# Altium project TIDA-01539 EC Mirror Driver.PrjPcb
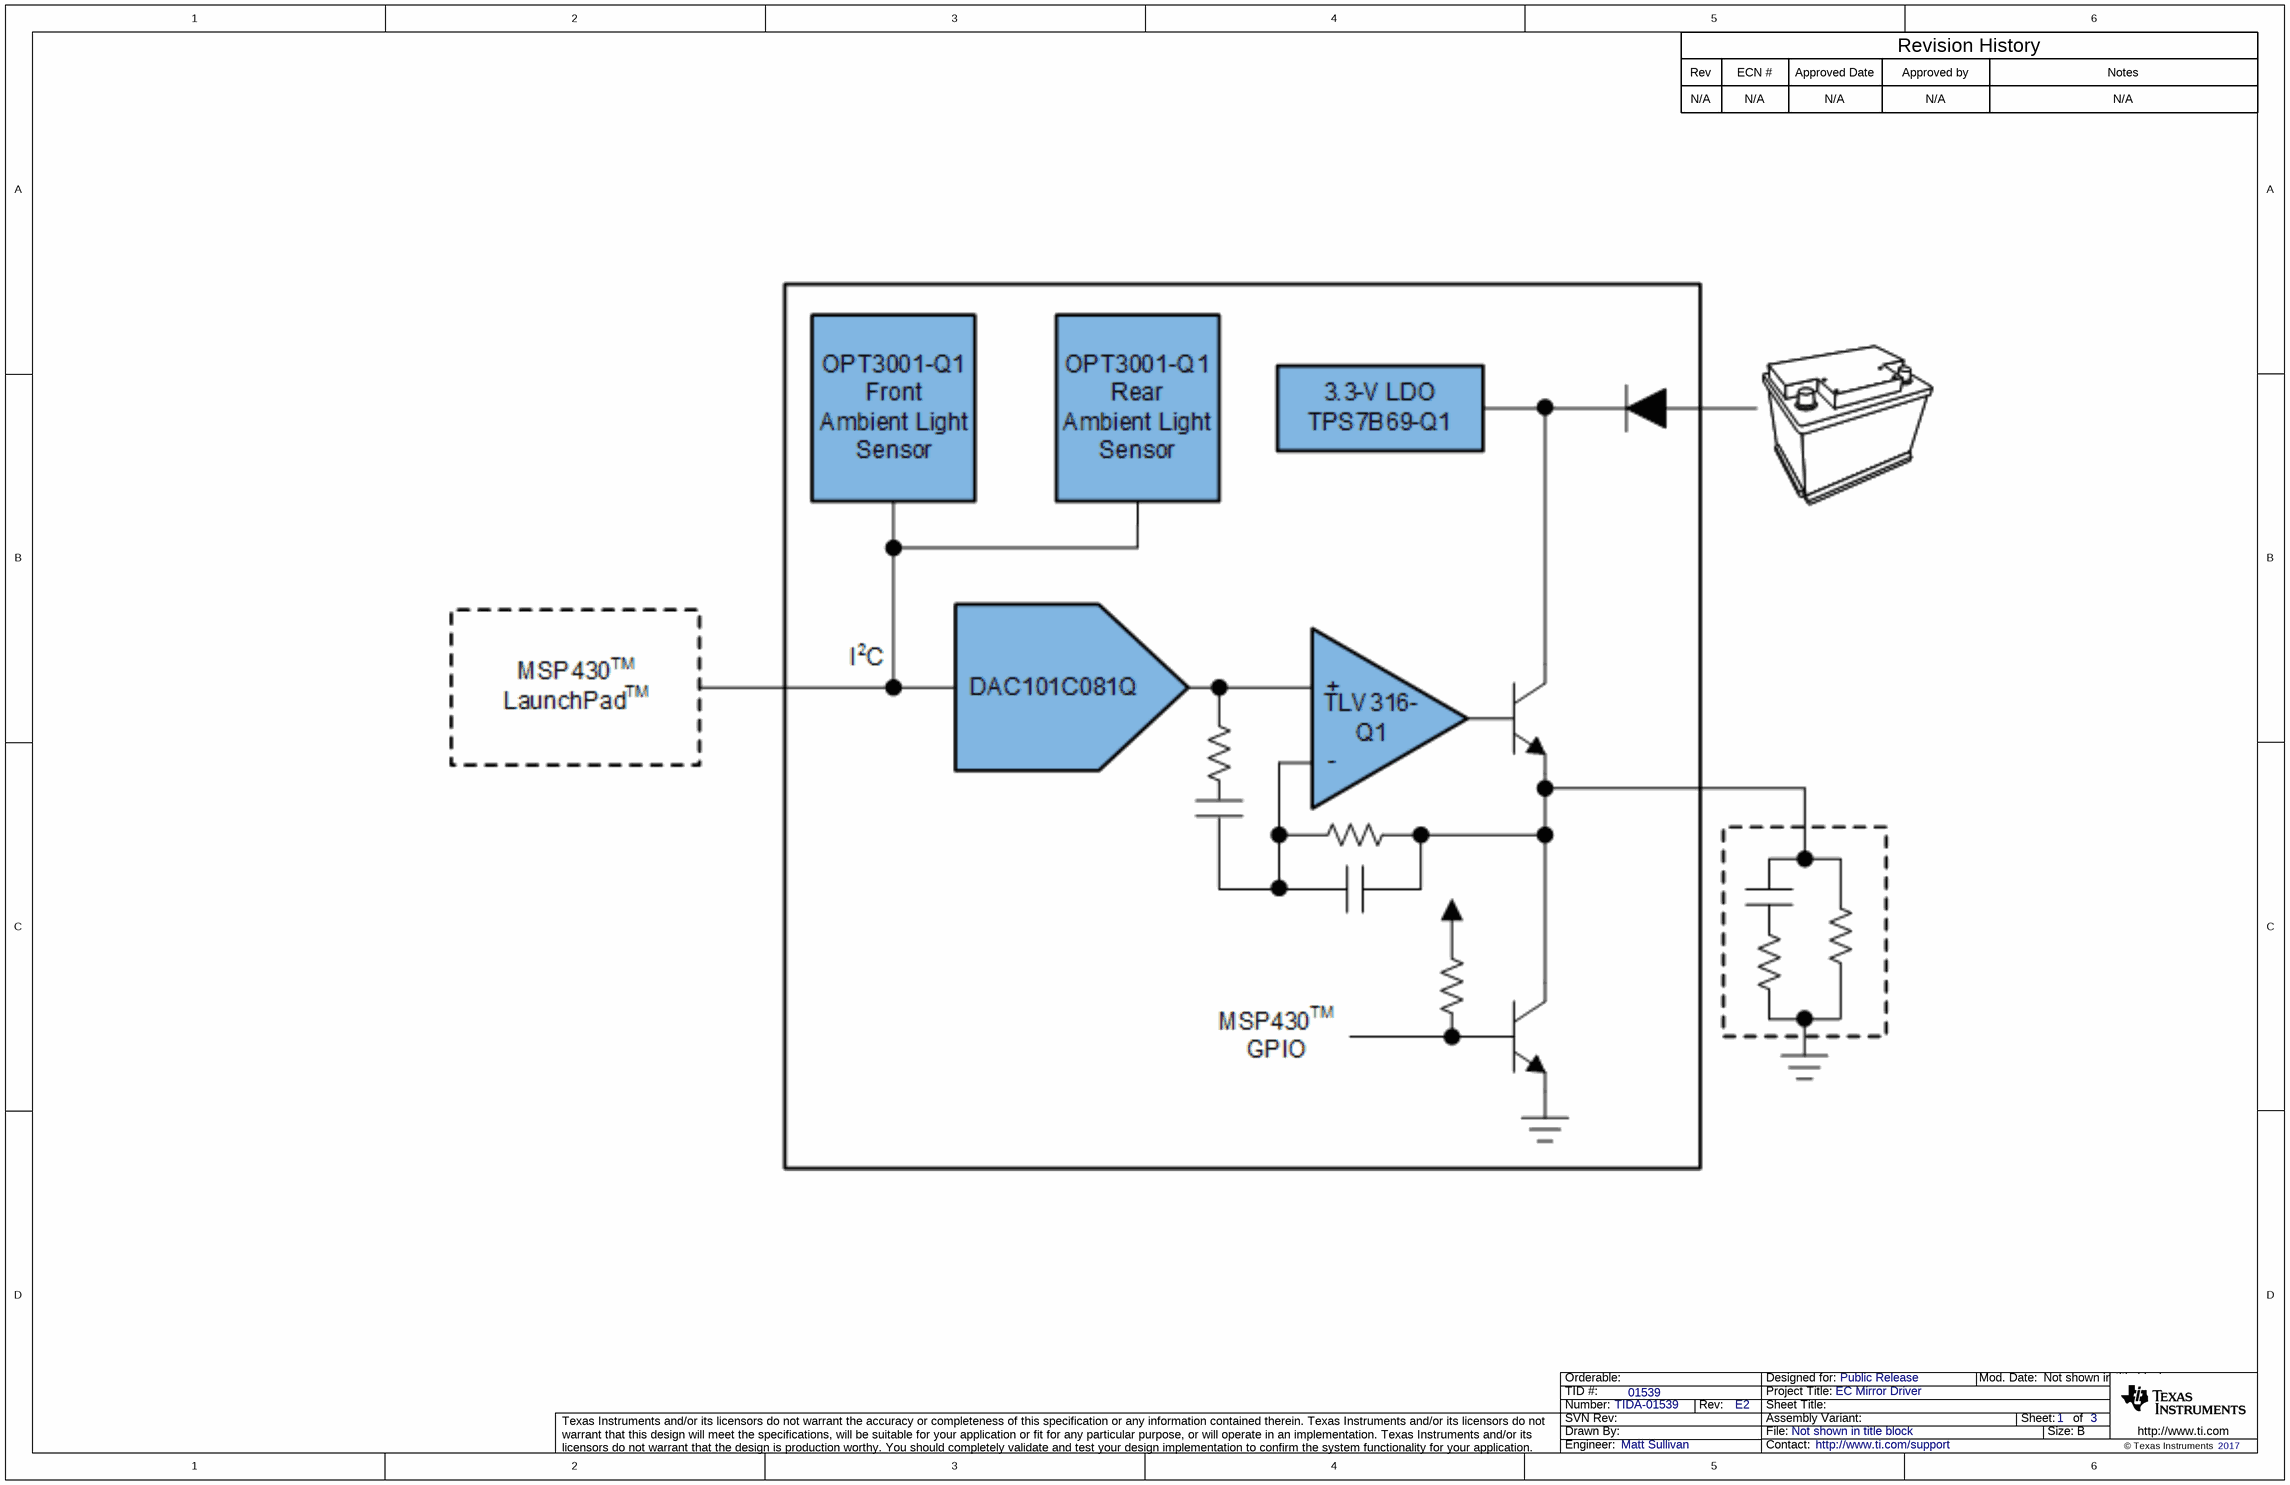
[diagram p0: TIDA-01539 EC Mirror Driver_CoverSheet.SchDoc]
CopyrightYear: 2017; PCB_Layout: Matt Sullivan; PCB_Rev: E2; PRJ_Customer: Public Release; PRJ_Engineer: Matt Sullivan; PRJ_Number: TIDA-01539; PRJ_Title: EC Mirror Driver; SCH_Rev: E2; TechSupport: http://www.ti.com/support; TID: 01539
3 sheets, 46 parts. Net scope: global (net labels, ports and power ports of the same name join across sheets).
Board file: TIDA-01539 EC Mirror Driver_PCB.PcbDoc
Sheets:
  TIDA-01539 EC Mirror Driver_CoverSheet.SchDoc
  TIDA-01539 EC Mirror Driver_EVM_Hardware.SchDoc
  TIDA-01539 EC Mirror Driver_Main.SchDoc

## Sheet TIDA-01539 EC Mirror Driver_CoverSheet.SchDoc
size 431 x 279 mm; Date: Not shown in title block; ApprovedBy: Not shown in title block; CheckedBy: Not shown in title block; Author: Not shown in title block; CompanyName: Not shown in title block; Engineer: Not shown in title block; Organization: Not shown in title block; Address1: Not shown in title block; Address2: Not shown in title block; Address3: Not shown in title block; Address4: Not shown in title block; DocumentNumber: 1; Revision: Use project parameter SCH_Rev; SheetNumber: 1; SheetTotal: 3; PageSetup: Record=PageOptions¦CenterHorizontal=True¦CenterVertical=True¦PrintScale=1.00¦XCorrection=1.00¦YCorrection=1.00¦PrintKind=0¦BorderSize=5000000¦LeftOffset=0¦BottomOffset=0¦Orientation=2¦PaperLength=1000¦PaperWidth=1000¦Scale=100¦PaperSource=15¦PrintQuality=600¦MediaType=1¦DitherType=10¦PaperKind=Letter¦PrintScaleMode=1

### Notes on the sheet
- Rev
- N/A
- ECN #
- Approved Date
- Approved by
- Revision History
- Notes

## Sheet TIDA-01539 EC Mirror Driver_EVM_Hardware.SchDoc
size 431 x 279 mm; Date: Not shown in title block; ApprovedBy: Not shown in title block; CheckedBy: Not shown in title block; Author: Not shown in title block; CompanyName: Not shown in title block; Engineer: Not shown in title block; Organization: Not shown in title block; Address1: Not shown in title block; Address2: Not shown in title block; Address3: Not shown in title block; Address4: Not shown in title block; DocumentNumber: 1; Revision: Use project parameter SCH_Rev; SheetNumber: 3; SheetTotal: 3; PageSetup: Record=PageOptions¦CenterHorizontal=True¦CenterVertical=True¦PrintScale=1.00¦XCorrection=1.00¦YCorrection=1.00¦PrintKind=0¦BorderSize=5000000¦LeftOffset=0¦BottomOffset=0¦Orientation=2¦PaperLength=1000¦PaperWidth=1000¦Scale=100¦PaperSource=15¦PrintQuality=600¦MediaType=1¦DitherType=10¦PaperKind=Letter¦PrintScaleMode=1
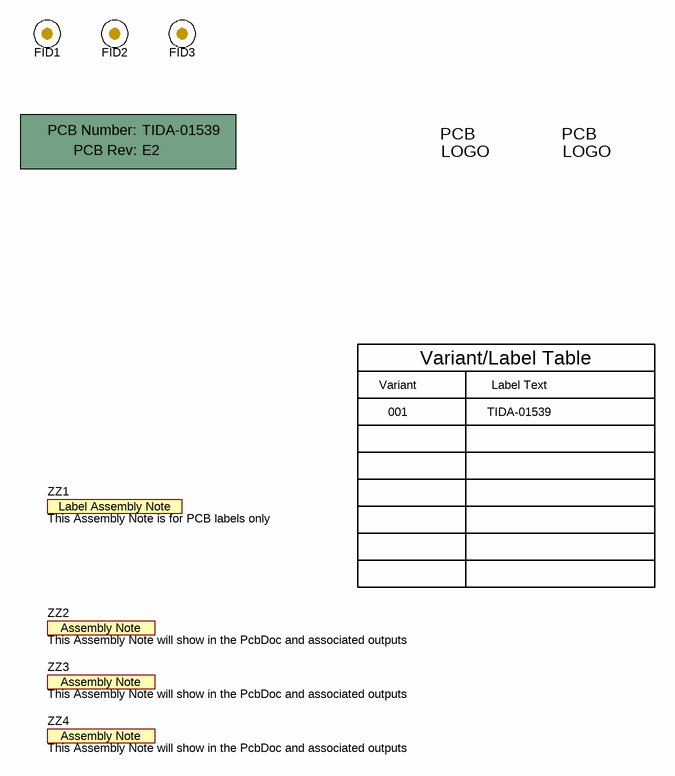
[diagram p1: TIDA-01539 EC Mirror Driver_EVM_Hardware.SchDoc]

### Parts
!PCB1  Printed Circuit Board  (value not drawn)  (mechanical)
FID1  Fiducial  [Fiducial10-20]  (value not drawn)
FID2  Fiducial  [Fiducial10-20]  (value not drawn)
FID3  Fiducial  [Fiducial10-20]  (value not drawn)
Logo2  Pb-Free Symbol  [Pb-Free_Overlay_Small]  (value not drawn)  (no BOM)
Logo3  FCC disclaimer  [FCC_disclaimer]  (value not drawn)  (no BOM)
ZZ1  This Assembly Note is for PCB labels only  [AssemblyNoteLabel]  (no BOM)
ZZ2  This Assembly Note will show in the PcbDoc and associated outputs  [AssemblyNote]  (no BOM)
ZZ3  This Assembly Note will show in the PcbDoc and associated outputs  [AssemblyNote]  (no BOM)
ZZ4  This Assembly Note will show in the PcbDoc and associated outputs  [AssemblyNote]  (no BOM)

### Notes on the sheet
- Variant
- Variant/Label Table
- Label Text
- 001
- TIDA-01539

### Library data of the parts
!PCB1 = PCB: Manufacturer: Any; PartNumber: TIDA-01539; SymbolCreator: a0412235
FID1-FID3 = Fiducial: Fiducial mark.  There is nothing to buy or mount.; SymbolCreator: codlsc
Logo2 = Pb-Free: SymbolCreator: a0412235
Logo3 = FCC_disclaimer: SymbolCreator: a0412235
ZZ1 = AssemblyNoteLabel: SymbolCreator: a0412235
ZZ2-ZZ4 = AssemblyNote: SymbolCreator: codlsc

## Sheet TIDA-01539 EC Mirror Driver_Main.SchDoc
size 431 x 279 mm; Date: Not shown in title block; ApprovedBy: Not shown in title block; CheckedBy: Not shown in title block; Author: Not shown in title block; CompanyName: Not shown in title block; Engineer: Not shown in title block; Organization: Not shown in title block; Address1: Not shown in title block; Address2: Not shown in title block; Address3: Not shown in title block; Address4: Not shown in title block; DocumentNumber: 1; Revision: Use project parameter SCH_Rev; SheetNumber: 2; SheetTotal: 3; PageSetup: Record=PageOptions¦CenterHorizontal=True¦CenterVertical=True¦PrintScale=1.00¦XCorrection=1.00¦YCorrection=1.00¦PrintKind=0¦BorderSize=5000000¦LeftOffset=0¦BottomOffset=0¦Orientation=2¦PaperLength=1000¦PaperWidth=1000¦Scale=100¦PaperSource=15¦PrintQuality=600¦MediaType=1¦DitherType=10¦PaperKind=Letter¦PrintScaleMode=1
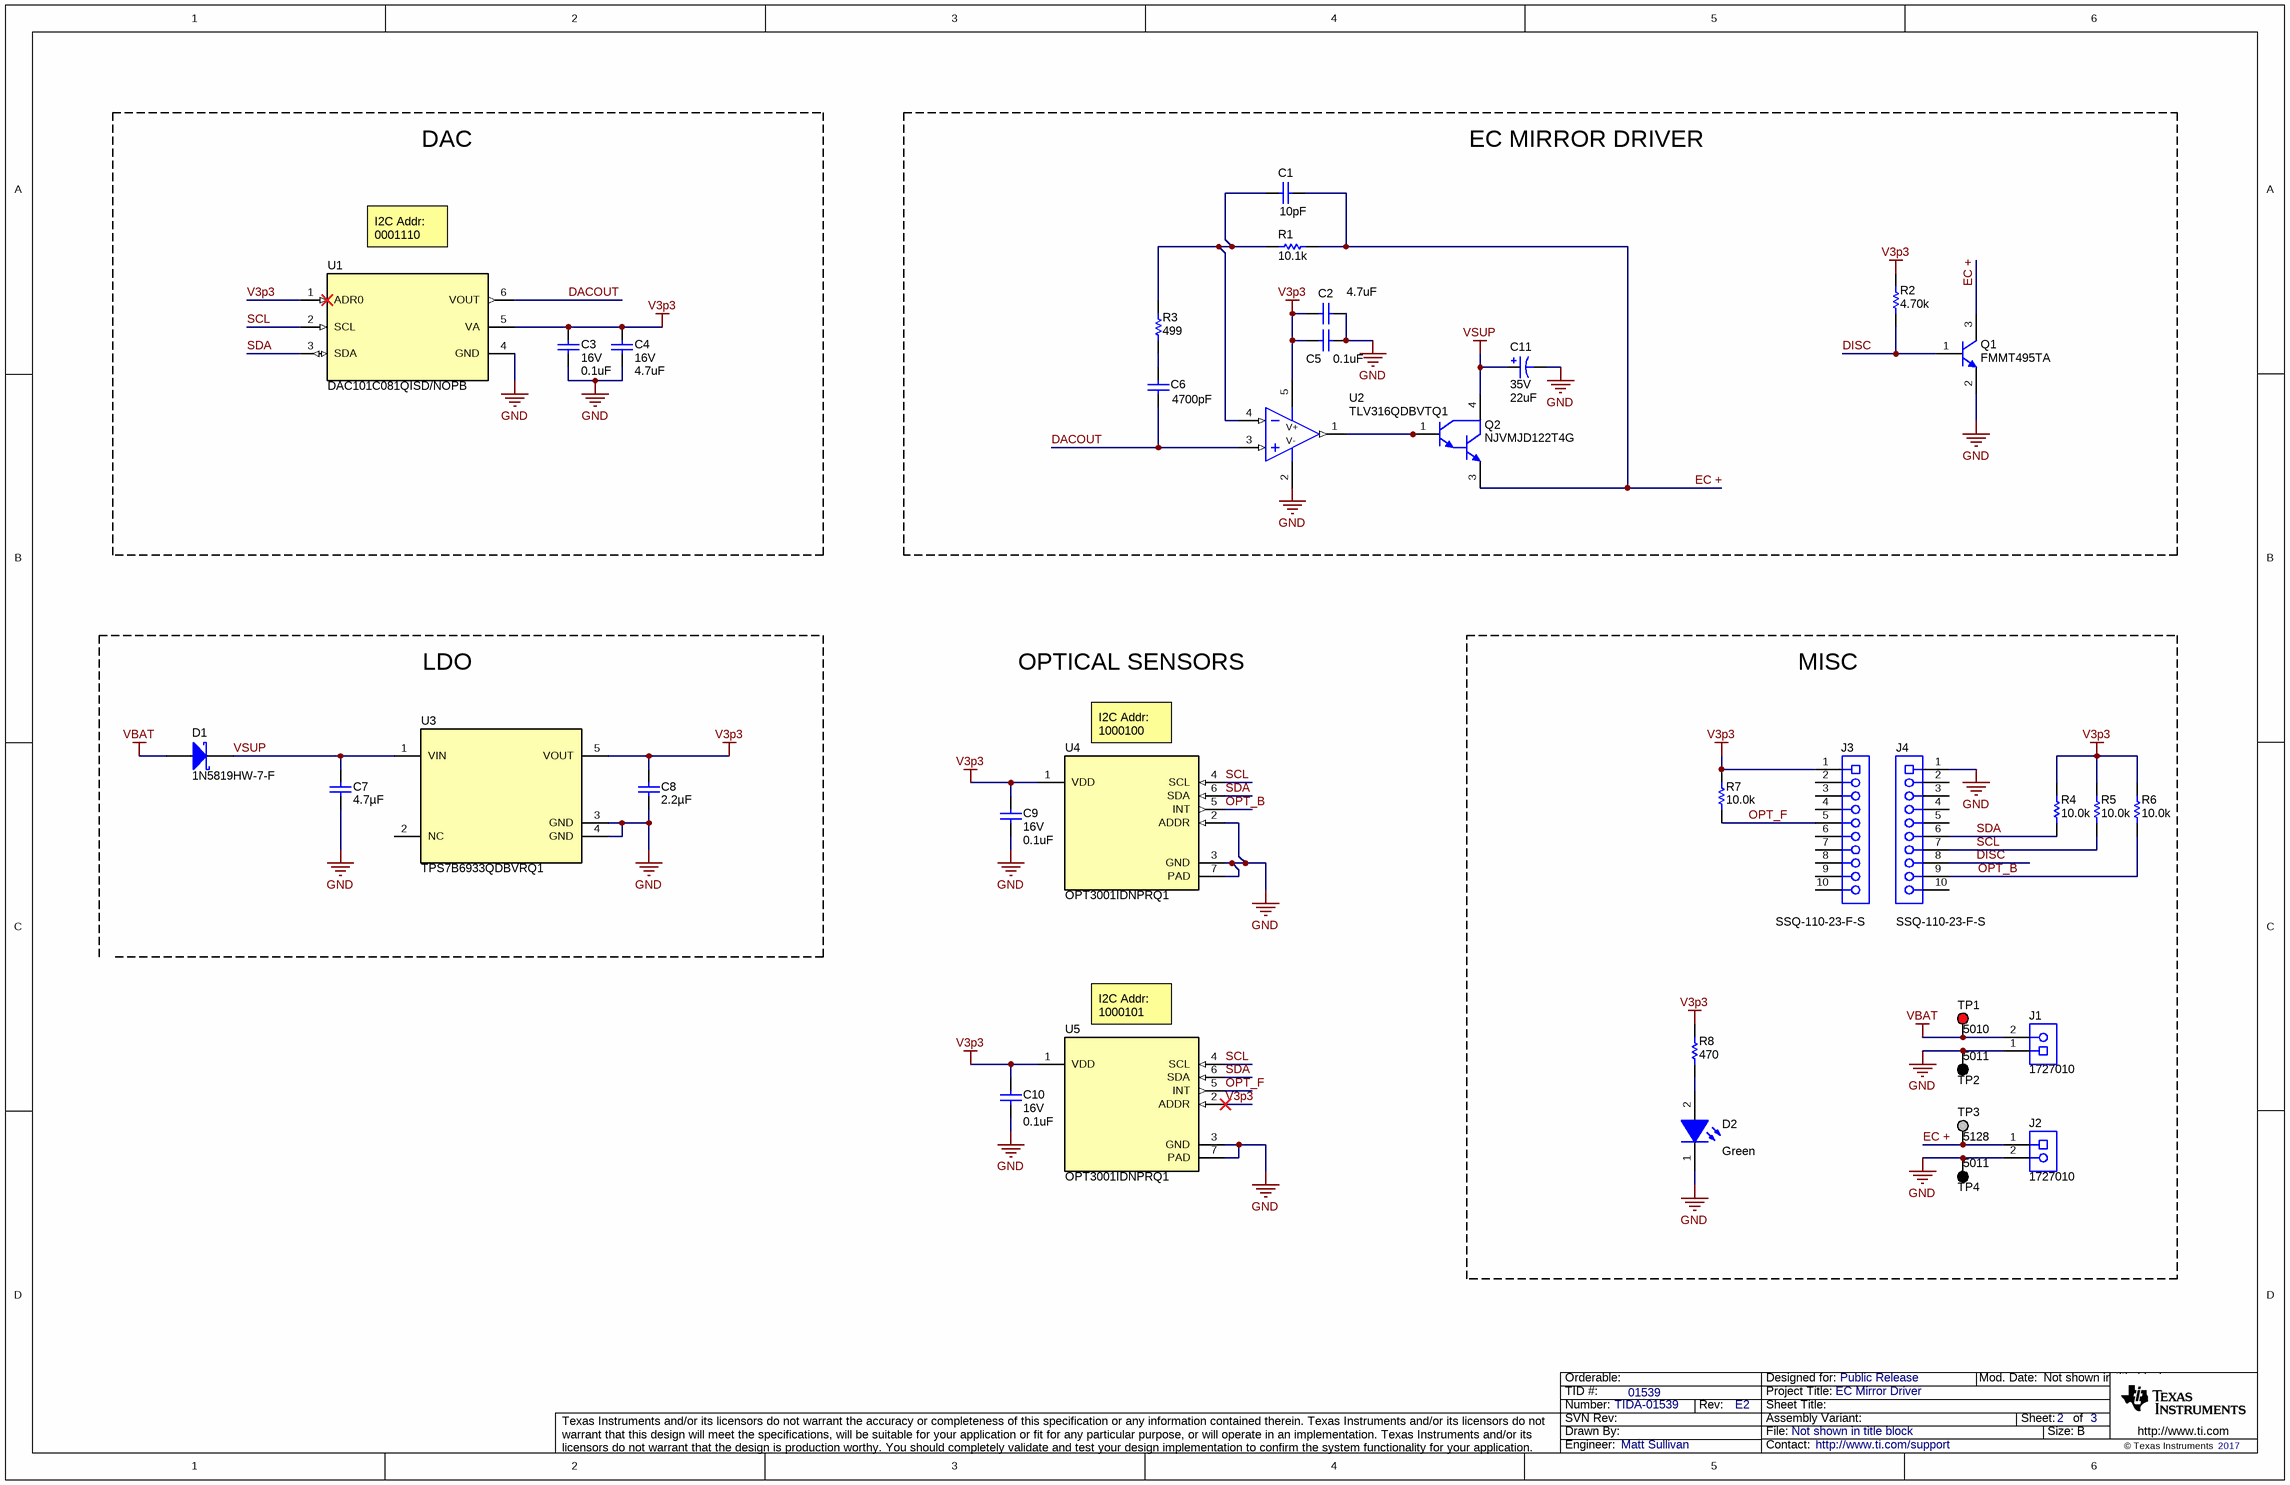
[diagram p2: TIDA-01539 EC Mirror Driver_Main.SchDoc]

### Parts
C1  ValueDisplayed: 10pF  [0603]  (hidden comment: 0603ZC100KAT2A)
C2  ValueDisplayed: 4.7uF  [0603]  (hidden comment: GRM188Z71C475KE21D)
C3  VDC_V: 16V  ValueDisplayed: 0.1uF  [0603]  (hidden comment: GCM188R71C104KA37J)
C4  VDC_V: 16V  ValueDisplayed: 4.7uF  [0603]  (hidden comment: GRM188Z71C475KE21D)
C5  ValueDisplayed: 0.1uF  [0603]  (hidden comment: GCM188R71C104KA37J)
C6  ValueDisplayed: 4700pF  [0603]  (hidden comment: GCM188R71H472KA37D)
C7  ValueDisplayed: 4.7µF  [0805_HV]  (hidden comment: GCM21BR71C475KA73K)
C8  ValueDisplayed: 2.2µF  [0805_HV]  (hidden comment: CGA4J3X7R1E225K125AB)
C9  VDC_V: 16V  ValueDisplayed: 0.1uF  [0603]  (hidden comment: GCM188R71C104KA37J)
C10  VDC_V: 16V  ValueDisplayed: 0.1uF  [0603]  (hidden comment: GCM188R71C104KA37J)
C11  VDC_V: 35V  ValueDisplayed: 22uF  [SM_RADIAL_C]  (hidden comment: EEE-FK1V220R)
D1  1N5819HW-7-F  [SOD-123]
D2  value Green  [WL-SMCW_GREEN]  (hidden comment: 150060GS75000)
J1  1727010  [PhoenixConact_1727010]
J2  1727010  [PhoenixConact_1727010]
J3  SSQ-110-23-F-S  [Samtec_SSQ-110-03-x-S]
J4  SSQ-110-23-F-S  [Samtec_SSQ-110-03-x-S]
Q1  FMMT495TA  [SOT-23]
Q2  NJVMJD122T4G  [DPAK]
R1  ValueDisplayed: 10.1k  [0603]  (hidden comment: RT0603DRE0710K1L)
R2  ValueDisplayed: 4.70k  [0603]  (hidden comment: RC0603FR-074K7L)
R3  ValueDisplayed: 499  [0603]  (hidden comment: CRCW0603499RFKEA)
R4  ValueDisplayed: 10.0k  [0603]  (hidden comment: RMCF0603FT10K0)
R5  ValueDisplayed: 10.0k  [0603]  (hidden comment: RMCF0603FT10K0)
R6  ValueDisplayed: 10.0k  [0603]  (hidden comment: RMCF0603FT10K0)
R7  ValueDisplayed: 10.0k  [0603]  (hidden comment: RMCF0603FT10K0)
R8  ValueDisplayed: 470  [0603]  (hidden comment: RC0603FR-07470RL)
TP1  5010  [Keystone5010]
TP2  5011  [Keystone5011]
TP3  5128  [Keystone5128]
TP4  5011  [Keystone5011]
U1  DAC101C081QISD/NOPB  [NGF0006A]
U2  TLV316QDBVTQ1  [DBV0005A_N]
U3  TPS7B6933QDBVRQ1  [DBV0005A_N]
U4  OPT3001IDNPRQ1  [DNP0006A]
U5  OPT3001IDNPRQ1  [DNP0006A]

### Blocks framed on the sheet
DAC: C3 C4 U1
EC MIRROR DRIVER: C1 C2 C5 C6 C11 Q1 Q2 R1-R3 U2
MISC: D2 J1-J4 R4-R8 TP1-TP4

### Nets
GND: C2.2 C3.2 C4.2 C5.2 C7.2 C8.2 C9.2 C10.2 C11.2(-) D2.1(K) J1.1 J2.2 J4.1 Q1.2(E) TP2.1 TP4.1 U1.4(GND) U2.2(V-) U3.3(GND) U3.4(GND) U4.2(ADDR) U4.3(GND) U4.7(PAD) U5.3(GND) U5.7(PAD)
V3p3: C2.1 C3.1 C4.1 C5.1 C8.1 C9.1 C10.1 J3.1 R2.2 R4.2 R5.2 R6.2 R7.2 R8.2 U1.1(ADR0) U1.5(VA) U2.5(V+) U3.5(VOUT) U4.1(VDD) U5.1(VDD) U5.2(ADDR)
VBAT: D1.2(A) J1.2 TP1.1
VSUP: C7.1 C11.1(+) D1.1(K) Q2.4(C) U3.1(VIN)
DACOUT: C6.2 U1.6(VOUT) U2.3(IN+)
DISC: J4.8 Q1.1(B) R2.1
EC +: C1.1 J2.1 Q1.3(C) Q2.3(E) R1.2 TP3.1
OPT_B: J4.9 R6.1 U4.5(INT)
OPT_F: J3.5 R7.1 U5.5(INT)
SCL: J4.7 R5.1 U1.2(SCL) U4.4(SCL) U5.4(SCL)
SDA: J4.6 R4.1 U1.3(SDA) U4.6(SDA) U5.6(SDA)
NetC1_2: C1.2 R1.1 R3.2 U2.4(IN-)
NetC6_1: C6.1 R3.1
NetD2_2: D2.2(A) R8.1
NetQ2_1: Q2.1(B) U2.1(OUT)

Not connected (* = marked no-connect by the designer): J3 2 3 4 6 7 8 9 10; J4 2 3 4 5 10; U3 2(NC)

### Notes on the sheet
- I2C Addr: 0001110
- LDO
- OPTICAL SENSORS
- (near U4) I2C Addr: 1000100
- (near U5) I2C Addr: 1000101

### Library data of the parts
C1 = CMP-0006811-2: CAP, CERM, 10 pF, 10 V, +/- 10%, X7R, 0603; Manufacturer: AVX; TaMin_C: -55°C; Polarized: N; SizeAreaWB_mm2: 4.68; Value1: Unknown; U/M: EA; Value: 10pF; TaMax_C: 125°C; SizeZ_mm: 1; SizeX_mm: 1.6; SizeY_mm: 0.8; Value2: 10V; SizeArea_mm2: 1.28; AEC Category: Q200
C2 = CMP-0064936-2: CAP, CERM, 4.7 uF, 16 V,+/- 10%, X7R, 0603; Manufacturer: MuRata; TaMin_C: -55°C; Polarized: N; SizeAreaWB_mm2: 4.68; Value1: Unknown; U/M: EA; Value: 4.7uF; TaMax_C: 125°C; SizeZ_mm: 1; SizeX_mm: 1.6; SizeY_mm: 0.8; Value2: 16V; SizeArea_mm2: 1.28; Cap_F: 4.7µF; AEC Category: Q200
C3 C9 C10 = CMP-0007135-2: CAP, CERM, 0.1 uF, 16 V, +/- 10%, X7R, AEC-Q200 Grade 1, 0603; Manufacturer: MuRata; TaMin_C: -55°C; Polarized: N; SizeAreaWB_mm2: 4.68; Value1: Unknown; U/M: EA; Value: 0.1uF; TaMax_C: 125°C; SizeZ_mm: 1; SizeX_mm: 1.6; SizeY_mm: 0.8; SizeArea_mm2: 1.28; AEC Qualified: Y; Cap_F: 100nF; AEC Category: Q200
C4 = CMP-0064936-2: CAP, CERM, 4.7 uF, 16 V,+/- 10%, X7R, 0603; Manufacturer: MuRata; TaMin_C: -55°C; Polarized: N; SizeAreaWB_mm2: 4.68; Value1: Unknown; U/M: EA; Value: 4.7uF; TaMax_C: 125°C; SizeZ_mm: 1; SizeX_mm: 1.6; SizeY_mm: 0.8; SizeArea_mm2: 1.28; Cap_F: 4.7µF; AEC Category: Q200
C5 = CMP-0007135-2: CAP, CERM, 0.1 uF, 16 V, +/- 10%, X7R, AEC-Q200 Grade 1, 0603; Manufacturer: MuRata; TaMin_C: -55°C; Polarized: N; SizeAreaWB_mm2: 4.68; Value1: Unknown; U/M: EA; Value: 0.1uF; TaMax_C: 125°C; SizeZ_mm: 1; SizeX_mm: 1.6; SizeY_mm: 0.8; Value2: 16V; SizeArea_mm2: 1.28; AEC Qualified: Y; Cap_F: 100nF; AEC Category: Q200
C6 = CMP-0007146-2: CAP, CERM, 4700 pF, 50 V, +/- 10%, X7R, AEC-Q200 Grade 1, 0603; Manufacturer: MuRata; TaMin_C: -55°C; Polarized: N; SizeAreaWB_mm2: 4.68; Value1: Unknown; U/M: EA; Value: 4700pF; TaMax_C: 125°C; SizeZ_mm: 1; SizeX_mm: 1.6; SizeY_mm: 0.8; Value2: 50V; SizeArea_mm2: 1.28; AEC Qualified: Y; Cap_F: 4.7nF; AEC Category: Q200
C7 = GCM21BR71C475KA73K: CAP, CERM, 4.7 µF, 16 V, +/- 10%, X7R, AEC-Q200 Grade 1, 0805; Manufacturer: MuRata; Polarized: N; CompType: Capacitor; Value: 4.7uF; U/M: EA; Cap_F: 0.0000047; Tolerance_%: 10; Value1: Unknown; VDC_V: 16; Value2: 16V; TaMin_C: -55; TaMax_C: 125; Cap_Case: 0805; SizeArea_mm2: 2.5; SizeAreaWB_mm2: 6.75; SizeX_mm: 2; SizeY_mm: 1.25; SizeZ_mm: 1.45; AEC Category: Q200; AEC Qualified: Y; AEC Grade: 1
C8 = CGA4J3X7R1E225K125AB: CAP, CERM, 2.2 µF, 25 V, +/- 10%, X7R, AEC-Q200 Grade 1, 0805; Manufacturer: TDK; Polarized: N; CompType: Capacitor; Value: 2.2uF; U/M: EA; Cap_F: 0.0000022; Tolerance_%: 10; Value1: Unknown; VDC_V: 25; Value2: 25V; TaMin_C: -55; TaMax_C: 125; Cap_Case: 0805; SizeArea_mm2: 2.5; SizeAreaWB_mm2: 6.75; SizeX_mm: 2; SizeY_mm: 1.25; SizeZ_mm: 1.45; AEC Category: Q200; AEC Qualified: Y; AEC Grade: 1
C11 = CMP-0010726-1: CAP, AL, 22 uF, 35 V, +/- 20%, 0.7 ohm, AEC-Q200 Grade 2, SMD; Manufacturer: Panasonic; TaMin_C: -55°C; ESR_ohm: 7d; Polarized: Y; SizeAreaWB_mm2: 62.05; Value1: 0.7 ohm; U/M: EA; Value: 22uF; TaMax_C: 105°C; SizeZ_mm: 5.4; SizeX_mm: 6.5; SizeY_mm: 5.3; Cap_Case: C; SizeArea_mm2: 34.45; CompType: Capacitor; Cap_F: 22µF; IRMS_A: 1.6dA; AEC Grade: 2; AEC Category: Q200
D1 = 1N5819HW-7-F: Diode, Schottky, 40 V, 1 A, SOD-123; Manufacturer: Diodes Inc.; U/M: EA; Vf_V: 0.45; Value: 40V; Value1: 1A; Value2: 0.45V; Io_A: 1; Vr_V: 40; TJmax_C: 125; SizeAreaWB_mm2: 13.095; SizeArea_mm2: 6.545; SizeX_mm: 3.85; SizeY_mm: 1.7; SizeZ_mm: 1.35; AEC Category: Q101
D2 = CMP-0002905-1: LED, Green, SMD; Manufacturer: Wurth Elektronik; Io_A: 20mA; Tjmax_C: 85°C; Value1: W; U/M: EA; Angle: 140; Vf_V: 3.2V; Type: InGaN
J1 J2 = 1727010: Conn Term Block, 2POS, 3.81mm, TH; Manufacturer: Phoenix Contact; SymbolCreator: a0412235; CompType: Terminal Block
J3 J4 = CMP-0055680-1: Receptacle, 2.54mm, 10x1, Gold, TH; Manufacturer: Samtec; CNHeader: FALSE; Current_A: 6.3A; Gender: Female; Cert_CSA: Y; CompType: Socket Strip; Row_Count: 1; Pitch_mm: 2.54; CT: TRUE
Q1 = CMP-0074710-1: Transistor, NPN, 150 V, 1 A, AEC-Q101, SOT-23; Manufacturer: Diodes Inc.; TaMin_C: -55°C; HfeMax: 300.0; SizeAreaWB_mm2: 14.0; Value1: 1 A; Vceo_V: 150V; U/M: EA; Value: 150 V; TaMax_C: 150°C; IcRated_A: 1A; SizeZ_mm: 1.1; SizeX_mm: 2.5; SizeY_mm: 3.0; SizeArea_mm2: 7.5; CompType: BJT; PNP: 0.0; AEC Qualified: Y; NPN: 1.0; Vcesat1_V: 3dV; AEC Category: Q101
Q2 = CMP-0077549-1: Transistor, NPN, 100 V, 8 A, AEC-Q101, DPAK; Manufacturer: ON Semiconductor; SizeAreaWB_mm2: 101.7114; NPN: 1; SizeArea_mm2: 64.8114; AEC Qualified: Y; IcRated_A: 8A; AEC Category: Q101; Value: 100 V; TaMax_C: 150°C; SizeZ_mm: 2.29; PNP: 0; Vceo_V: 100V; TaMin_C: -65°C; SizeY_mm: 6.54; U/M: EA; Value1: 8 A; CompType: BJT; Vcesat1_V: 2V; SizeX_mm: 9.91
R1 = CMP-0024579-1: RES, 10.1 k, 0.5%, 0.1 W, 0603; Manufacturer: Yageo America; Power_W: 100mW; TempCo: 50 ppm/C; Value_Code: 10k1; U/M: EA; Value: 10.1k; EIA_Code: E192; SizeX_mm: 1.6; SizeY_mm: 0.8; SizeZ_mm: 1; Value2: 0.1W; SizeArea_mm2: 1.28; VDC_V: 75V; AEC Category: Q200
R2 = CMP-0023153-2: RES, 4.70 k, 1%, 0.1 W, 0603; Manufacturer: Yageo America; Power_W: 100mW; TempCo: 200 ppm/C; Value_Code: 4k70; U/M: EA; Value: 4.70k; Res_ohm: 4.7k; SizeX_mm: 1.6; SizeY_mm: 0.8; SizeZ_mm: 1; Value2: 0.1W; SizeArea_mm2: 1.28; VDC_V: 150V; AEC Category: Q200
R3 = CMP-0022446-3: RES, 499, 1%, 0.1 W, 0603; Manufacturer: Vishay-Dale; Power_W: 100mW; TempCo: 100 ppm/C; Value_Code: 499R; U/M: EA; Value: 499; EIA_Code: E96; SizeX_mm: 1.6; SizeY_mm: 0.8; SizeZ_mm: 1; Value2: 0.1W; SizeArea_mm2: 1.28; VDC_V: 75V; AEC Category: Q200
R4-R7 = CMP-0023341-2: RES, 10.0 k, 1%, 0.1 W, AEC-Q200 Grade 0, 0603; Manufacturer: Stackpole Electronics Inc; Power_W: 100mW; TempCo: 100 ppm/C; Value_Code: 10k0; U/M: EA; Value: 10.0k; EIA_Code: E96; Res_ohm: 10k; SizeX_mm: 1.6; SizeY_mm: 0.8; SizeZ_mm: 1; Value2: 0.1W; SizeArea_mm2: 1.28; AEC Qualified: Y; VDC_V: 75V; AEC Grade: 0; AEC Category: Q200
R8 = CMP-0023129-2: RES, 470, 1%, 0.1 W, 0603; Manufacturer: Yageo America; Power_W: 100mW; TempCo: 200 ppm/C; Value_Code: 470R; U/M: EA; Value: 470; SizeX_mm: 1.6; SizeY_mm: 0.8; SizeZ_mm: 1; Value2: 0.1W; SizeArea_mm2: 1.28; VDC_V: 150V; AEC Category: Q200
TP1 = CMP-0055147-1: Test Point, Multipurpose, Red, TH; Manufacturer: Keystone; CNHeader: FALSE; Green_Lifecycle: Active; Green_REACh: Passed; ContactFinish: Silver; CT: TRUE
TP2 TP4 = CMP-0055148-1: Test Point, Multipurpose, Black, TH; Manufacturer: Keystone; CNHeader: FALSE; Green_Lifecycle: Active; Green_REACh: Passed; ContactFinish: Silver; CT: TRUE
TP3 = CMP-0055159-1: Test Point, Multipurpose, Grey, TH; Manufacturer: Keystone; CNHeader: FALSE; Green_Lifecycle: Active; Green_REACh: Passed; ContactFinish: Silver; CT: TRUE
U1 = CMP-0080599-1: 10-Bit Micro Power Dig-to-Analog Converter, NGF0006A (WSON-6); Alternate PartNumber: DAC101C081QISDX/NOPB; Alternate Manufacturer: Texas Instruments; SizeAreaWB_mm2: 11.2; SizeZ_mm: 0.8; SizeX_mm: 2.5; SizeY_mm: 2.2; SizeArea_mm2: 5.5; CompType: IC; AEC Qualified: Y; AEC Category: Q200
U2 = CMP-0079805-1: 10-MHz, Rail-to-Rail Input/Output, Low-Voltage, 1.8-V CMOS Operational Amplifier, DBV0005A (SOT-23-5); Alternate PartNumber: TLV316QDBVRQ1; Alternate Manufacturer: Texas Instruments; SizeAreaWB_mm2: 14.82; SizeZ_mm: 1.45; SizeX_mm: 2.8; SizeY_mm: 2.9; SizeArea_mm2: 8.12; CompType: IC; AEC Qualified: Y; AEC Category: Q200
U3 = TPS7B6933QDBVRQ1: High Voltage Ultra Low Iq - Low Drop Out Regulator, DBV0005A (SOT-23-5); Manufacturer: Texas Instruments; SymbolCreator: Altium; SizeArea_mm2: 8.12; SizeAreaWB_mm2: 14.82; SizeX_mm: 2.8; SizeY_mm: 2.9; SizeZ_mm: 1.45; CompType: IC; U/M: EA
U4 U5 = CMP-0074867-1: Ambient Light Sensor (ALS), DNP0006A (USON-6); Alternate PartNumber: OPT3001IDNPTQ1; Alternate Manufacturer: Texas Instruments; SizeAreaWB_mm2: 9.0; U/M: EA; SizeZ_mm: 0.65; SizeX_mm: 2.0; SizeArea_mm2: 4.0; CompType: IC

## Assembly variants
001: not fitted FID1 FID2 FID3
